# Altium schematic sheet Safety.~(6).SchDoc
size A
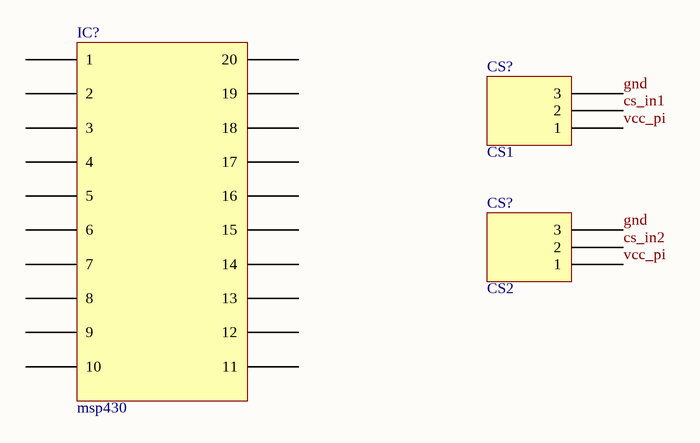
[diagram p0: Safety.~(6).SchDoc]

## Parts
(Parts that share a designator on the sheet are numbered #1, #2 ... from top to bottom, then left to right.)
CS?#1  CS1  [ACS712]
CS?#2  CS2  [ACS712]
IC?  msp430  [msp430]

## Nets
cs_in1: CS?#1.2
cs_in2: CS?#2.2
gnd: CS?#1.3 CS?#2.3
vcc_pi: CS?#1.1 CS?#2.1

Not connected (* = marked no-connect by the designer): IC? 1 2 3 4 5 6 7 8 9 10 11 12 13 14 15 16 17 18 19 20

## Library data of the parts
CS?#1 CS?#2 = ACS712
